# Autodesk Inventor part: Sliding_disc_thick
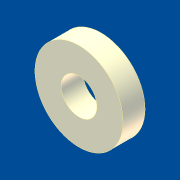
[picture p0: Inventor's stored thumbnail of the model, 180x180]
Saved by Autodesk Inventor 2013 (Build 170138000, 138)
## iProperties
Shininess: 31.0
Length Units: 11269
Angle Units: 11279
Time Units: 11290
Mass Units: 11283
Length Display Precision: 3
Angle Display Precision: 2
Created: 2001-04
Part Number: Sliding_disc_thick
Material: Standard
Document SubType Name: Modellieren
Designer: dl
Density: 1 g/cm^3
Density: 0.0
Volumn: 0.0
Area: 0.0
PropertySet Name: Model Information
Control State: 0
Master: False
Checked Out: False
Author: dl
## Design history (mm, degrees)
body "Solid1"
sketch "Sketch1"
  geometry: C1 r 8 at (0, 0); C2 r 3.25 at (0, 0)
  constraints: 2 centre point, 1 coincident
  dimensions: "d0" = 16 diameter of C1; "d1" = 6.5 diameter of C2
extrude "Extrusion1" new body sketch "Sketch1" distance "d2" = 4; taper "d3" = 0 deg
